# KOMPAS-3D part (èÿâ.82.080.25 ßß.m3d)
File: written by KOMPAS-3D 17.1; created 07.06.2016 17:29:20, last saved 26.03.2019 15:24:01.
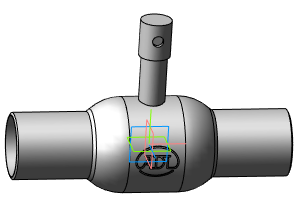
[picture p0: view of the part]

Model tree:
1. Операция без истории:5  (labels: Сталь 20  ГОСТ 1050-88)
